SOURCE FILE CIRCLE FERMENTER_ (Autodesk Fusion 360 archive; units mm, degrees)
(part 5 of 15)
sketch "Schizzo3" plane through (-180, 0, 0) normal (-1, 0, 0) x axis (0, -1, 0)
  line L1 (-70, 14) -> (70, 14)
  line L2 (69.3077, 4.1796) -> (61.1321, 9.9042)
  line L3 (70.7767, 9.9042) -> (61.1321, 9.9042)
  line L4 (69.3077, 23.8204) -> (61.1321, 18.0958)
  line L5 (-43.1586, 69.1121) -> (-34.1131, 64.8941)
  line L6 (-26.1492, 78.9324) -> (-27.019, 68.9898)
  line L7 (-26.1492, -50.9324) -> (-27.019, -40.9898)
  line L8 (-43.1586, -41.1121) -> (-34.1131, -36.8941)
  circle C1 centre (0, 14) radius 70
  circle C2 centre (0, 14) radius 78
  circle C3 centre (0, 14) radius 70
  arc A1 centre (64, 14) radius 5 clockwise from (66.8679, 9.9042) to (61.1321, 18.0958)
  arc A2 centre (-32, 69.4256) radius 5 clockwise from (-29.8869, 73.9572) to (-34.1131, 64.8941)
  arc A3 centre (-32, -41.4256) radius 5
  point P4 (70, 14)
  point P5 (-70, 14)
  point P3 (0, 14)
  point P6 (64, 14)
  point P7 (61.1321, 9.9042)
  point P10 (61.1321, 18.0958)
  point P8 (69.3077, 4.1796)
  point P11 (69.3077, 23.8204)
  point P12 (66.8679, 9.9042)
  coincident C3 P4
  coincident C3 P5
  horizontal L1
  coincident P3 L1
  coincident L1 P6
  horizontal L3
  coincident P7 A1
  tangent L2 A1
  symmetric L1 P7 P10
  symmetric L1 P8 P11
  coincident L3 P12
  coincident C3 P11
  dimension "d1125" diameter A1 = 10
  dimension "d1126" distance P4 P6 = 6
  dimension "d1127" angle L2 L3 = 35
  dimension "d1129" C-Pattern1-Angle = 360
extrude "Estrusione4" add sketch "Schizzo3" profile of C1 C3 A1 L2 L4 L5 A2 L6 L7 A3 L8 against normal blind 15
sketch "Schizzo4" plane through (-180, 0, 0) normal (-1, 0, 0) x axis (0, -1, 0)
  line L1 (61.1321, 18.0958) -> (69.3077, 23.8204)
  line L2 (69.3077, 4.1796) -> (61.1321, 9.9042)
  line L3 (-27.019, -40.9898) -> (-26.1492, -50.9324)
  line L4 (-43.1586, -41.1121) -> (-34.1131, -36.8941)
  line L5 (-34.1131, 64.8941) -> (-43.1586, 69.1121)
  line L6 (-26.1492, 78.9324) -> (-27.019, 68.9898)
  arc A1 centre (0, 14) radius 70 clockwise from (-26.1492, 78.9324) to (69.3077, 23.8204)
  arc A2 centre (64, 14) radius 5 clockwise from (61.1321, 9.9042) to (61.1321, 18.0958)
  arc A3 centre (0, 14) radius 70 clockwise from (69.3077, 4.1796) to (-26.1492, -50.9324)
  arc A4 centre (-32, -41.4256) radius 5 clockwise from (-34.1131, -36.8941) to (-27.019, -40.9898)
  arc A5 centre (0, 14) radius 70 clockwise from (-43.1586, -41.1121) to (-43.1586, 69.1121)
  arc A6 centre (-32, 69.4256) radius 5 clockwise from (-27.019, 68.9898) to (-34.1131, 64.8941)
  circle C1 centre (0, 14) radius 78
hole "Foratura1" HoleDepth 12 HoleDiameter 3.5 TipAngle 180
position "Posizione1"
sketch "Schizzo4" plane through (-180, 0, 0) normal (1, 0, 0) x axis (0, 1, 0)
  line L1 (-36.4, -31.9) -> (36.4, -31.9)
  line L2 (-42.9, 53.4) -> (-42.9, -25.4)
  line L3 (36.4, 59.9) -> (-36.4, 59.9)
  line L4 (42.9, -25.4) -> (42.9, 53.4)
  line L5 (65, -86.5) -> (-65, -86.5)
  curve K1 (88, -63.5) -> (65, -86.5)
  line L6 (88, -56.2402) -> (88, -63.5)
  line L7 (79.4522, -45.6213) -> (86.5355, -52.7047)
  line L8 (86.5355, -34.2953) -> (79.4522, -41.3787)
  line L9 (88, 58.7598) -> (88, -30.7598)
  line L10 (79.4522, 69.3787) -> (86.5355, 62.2953)
  line L11 (86.5355, 80.7047) -> (79.4522, 73.6213)
  line L12 (88, 91.5) -> (88, 84.2402)
  curve K2 (65, 114.5) -> (88, 91.5)
  line L13 (-65, 114.5) -> (65, 114.5)
  curve K3 (-65, 114.5) -> (-88, 91.5)
  line L14 (-88, 84.2402) -> (-88, 91.5)
  line L15 (-79.4522, 73.6213) -> (-86.5355, 80.7047)
  line L16 (-86.5355, 62.2953) -> (-79.4522, 69.3787)
  line L17 (-88, -30.7598) -> (-88, 58.7598)
  line L18 (-79.4522, -41.3787) -> (-86.5355, -34.2953)
  line L19 (-86.5355, -52.7047) -> (-79.4522, -45.6213)
  line L20 (-88, -63.5) -> (-88, -56.2402)
  curve K4 (-88, -63.5) -> (-65, -86.5)
  arc A1 centre (-36.4, -25.4) radius 6.5 clockwise from (-36.4, -31.9) to (-42.9, -25.4)
  arc A2 centre (-36.4, 53.4) radius 6.5 clockwise from (-42.9, 53.4) to (-36.4, 59.9)
  arc A3 centre (36.4, 53.4) radius 6.5 clockwise from (36.4, 59.9) to (42.9, 53.4)
  arc A4 centre (36.4, -25.4) radius 6.5 clockwise from (42.9, -25.4) to (36.4, -31.9)
  circle C1 centre (25, 110.9) radius 1.75
  circle C2 centre (84.4, -11) radius 1.75
  circle C3 centre (25, -82.9) radius 1.75
  circle C4 centre (84.4, 39) radius 1.75
  circle C5 centre (-84.4, 39) radius 1.75
  circle C6 centre (-25, -82.9) radius 1.75
  circle C7 centre (-84.4, -11) radius 1.75
  circle C8 centre (-25, 110.9) radius 1.75
  arc A5 centre (83, -56.2402) radius 5 clockwise from (86.5355, -52.7047) to (88, -56.2402)
  arc A6 centre (81.5735, -43.5) radius 3 clockwise from (79.4522, -45.6213) to (79.4522, -41.3787)
  arc A7 centre (83, -30.7598) radius 5 clockwise from (88, -30.7598) to (86.5355, -34.2953)
  arc A8 centre (83, 58.7598) radius 5 clockwise from (86.5355, 62.2953) to (88, 58.7598)
  arc A9 centre (81.5735, 71.5) radius 3 clockwise from (79.4522, 69.3787) to (79.4522, 73.6213)
  arc A10 centre (83, 84.2402) radius 5 clockwise from (88, 84.2402) to (86.5355, 80.7047)
  arc A11 centre (-83, 84.2402) radius 5 clockwise from (-86.5355, 80.7047) to (-88, 84.2402)
  arc A12 centre (-81.5735, 71.5) radius 3 clockwise from (-79.4522, 73.6213) to (-79.4522, 69.3787)
  arc A13 centre (-83, 58.7598) radius 5 clockwise from (-88, 58.7598) to (-86.5355, 62.2953)
  arc A14 centre (-83, -30.7598) radius 5 clockwise from (-86.5355, -34.2953) to (-88, -30.7598)
  arc A15 centre (-81.5735, -43.5) radius 3 clockwise from (-79.4522, -41.3787) to (-79.4522, -45.6213)
  arc A16 centre (-83, -56.2402) radius 5 clockwise from (-88, -56.2402) to (-86.5355, -52.7047)
  circle C9 centre (55.4256, 46) radius 1.75
  circle C10 centre (-55.4256, 46) radius 1.75
  circle C11 centre (0, -50) radius 1.75
extrude "Estrusione2" cut sketch "Schizzo4" profile of C9 C10 C11 against normal blind 49.402
thread "Filettatura1"
sketch "Schizzo1" plane through (0, 0, -86.9) normal (0, 0, -1) x axis (1, 0, 0)
  line L1 (95, -64.5) -> (-95, -64.5)
  curve K1 (95, -64.5) -> (134.5, -25)
  line L2 (134.5, 25) -> (134.5, -25)
  curve K2 (95, 64.5) -> (134.5, 25)
  line L3 (-95, 64.5) -> (95, 64.5)
  curve K3 (-95, 64.5) -> (-134.5, 25)
  line L4 (-134.5, -25) -> (-134.5, 25)
  curve K4 (-95, -64.5) -> (-134.5, -25)
  curve K5 (95, -55) -> (125, -25)
  line L5 (95, -55) -> (0, -55)
  line L6 (-95, -55) -> (0, -55)
  curve K6 (-95, -55) -> (-125, -25)
  line L7 (-125, 25) -> (-125, -25)
  curve K7 (-95, 55) -> (-125, 25)
  line L8 (-95, 55) -> (0, 55)
  line L9 (95, 55) -> (0, 55)
  curve K8 (95, 55) -> (125, 25)
  line L10 (125, -25) -> (125, 25)
  line L11 (-125, 0) -> (125, 0)
  line L12 (100, -30) -> (100, 0)
  line L13 (20, -30) -> (100, -30)
  line L14 (-100, -15) -> (20, -30)
  line L15 (-100, 0) -> (-100, -15)
  line L16 (100, 30) -> (100, 0)
  line L17 (20, 30) -> (100, 30)
  line L18 (-100, 15) -> (20, 30)
  line L19 (-100, 0) -> (-100, 15)
  line L20 (-98.4, 0) -> (-98.4, -13.5875)
  line L21 (-98.4, 0) -> (-98.4, 13.5875)
  line L22 (-98.4, 13.5875) -> (20.0996, 28.4)
  line L23 (20.0996, 28.4) -> (98.4, 28.4)
  line L24 (98.4, 28.4) -> (98.4, 0)
  line L25 (98.4, -28.4) -> (98.4, 0)
  line L26 (20.0996, -28.4) -> (98.4, -28.4)
  line L27 (-98.4, -13.5875) -> (20.0996, -28.4)
  circle C1 centre (-130, 25) radius 1.75
  circle C2 centre (-95, 60) radius 1.75
  circle C3 centre (-32, 60) radius 1.75
  circle C4 centre (-32, -60) radius 1.75
  circle C5 centre (-95, -60) radius 1.75
  circle C6 centre (-130, -25) radius 1.75
  circle C7 centre (130, -25) radius 1.75
  circle C8 centre (95, -60) radius 1.75
  circle C9 centre (32, -60) radius 1.75
  circle C10 centre (32, 60) radius 1.75
  circle C11 centre (95, 60) radius 1.75
  circle C12 centre (130, 25) radius 1.75
  point P34 (125, 0)
  point P35 (-125, 0)
  point P36 (100, 0)
  point P40 (-100, 0)
  point P41 (100, 0)
  point P37 (100, -30)
  point P42 (100, 30)
  point P38 (20, -30)
  point P43 (20, 30)
  point P39 (-100, -15)
  point P44 (-100, 15)
  point P45 (-100, 0)
  midpoint L10 P34
  midpoint L7 P35
  coincident L11 P36
  perpendicular L11 L12
  perpendicular L12 L13
  coincident L11 P40
  perpendicular L11 L15
  symmetric L11 P36 P41
  symmetric L11 P37 P42
  symmetric L11 P38 P43
  symmetric L11 P39 P44
  symmetric L11 P40 P45
  dimension "d1137" distance L10 L12 = 25
  dimension "d1138" distance L5 L13 = 25
  dimension "d1139" distance P37 P38 = 80
  dimension "d1140" distance P39 P40 = 15
  dimension "d1142" distance L7 L15 = 25
  dimension "d1143" = 1.6
extrude "Estrusione1" new body sketch "Schizzo1" profile of L12 L13 L14 L15 L16 L17 L18 L19 L21 L20 L23 L22 L24 L25 L26 L27 along normal blind 15
fillet "Raccordo1" radius 10 100
fillet "Raccordo2" radius 5
shell "Svuotamento1" innerThickness 1.6
work_plane "Piano di lavoro1" AlongDistance -30
sketch "Schizzo2" plane through (70, 0, 0) normal (1, 0, 0) x axis (0, 1, 0)
  line L1 (-30, -101.9) -> (-30, -86.9)
  line L2 (-30, -86.9) -> (-30, -101.9)
  line L3 (-38, -86.9) -> (-30, -86.9)
  curve K1 (-38, -91.9) -> (-38, -86.9)
  curve K2 (-34, -94.4) -> (-38, -91.9)
  curve K3 (-30, -96.9) -> (-34, -94.4)
  curve K4 (-30, -101.9) -> (-30, -96.9)
  curve K5 (-30, -101.9) -> (-38, -86.9)
  line L4 (-29.6, -86.9) -> (-30, -86.9)
  line L5 (-29.6, -101.9) -> (-29.6, -86.9)
  line L6 (-30, -101.9) -> (-29.6, -101.9)
  point P2 (-30, -86.9)
  point P4 (-30, -86.9)
  point P8 (-30, -96.9)
  point P9 (-30, -86.9)
  point P3 (-30, -101.9)
  point P12 (-30, -101.9)
  point P5 (-38, -86.9)
  point P6 (-38, -91.9)
  point P10 (-29.6, -86.9)
  coincident P2 P4
  perpendicular L2 L3
  coincident L1 P8
  vertical K1
  parallel K2 K3
  equal K2 K3
  coincident P2 P9
  perpendicular L2 L4
  coincident P3 P12
  vertical L5
  horizontal L6
  dimension "d1154" distance P4 P5 = 8
  dimension "d1155" distance P3 P8 = 5
  dimension "d1156" distance P5 P6 = 5
  dimension "d1163" distance P9 P10 = 0.4
sweep "Sweep1" sketch "Schizzo2" TwistAngle 0 TaperAngle 0
sketch "Schizzo3" plane through (0, 0, -86.9) normal (0, 0, 1) x axis (-1, 0, 0)
  line L1 (-108, -20) -> (-108, 20)
  curve K1 (-90, -38) -> (-108, -20)
  line L2 (-26.2258, -38) -> (-90, -38)
  line L3 (96.6125, -23.4857) -> (-12.83, -37.166)
  line L4 (108, 10.5861) -> (108, -10.5861)
  line L5 (-12.83, 37.166) -> (96.6125, 23.4857)
  line L6 (-90, 38) -> (-26.2258, 38)
  curve K2 (-108, 20) -> (-90, 38)
  line L7 (-90, -28.4) -> (-26.2258, -28.4)
  curve K3 (-98.4, -20) -> (-90, -28.4)
  line L8 (-98.4, 20) -> (-98.4, -20)
  curve K4 (-90, 28.4) -> (-98.4, 20)
  line L9 (-26.2258, 28.4) -> (-90, 28.4)
  line L10 (95.4217, 13.9598) -> (-14.0208, 27.6401)
  line L11 (98.4, -10.5861) -> (98.4, 10.5861)
  line L12 (-14.0208, -27.6401) -> (95.4217, -13.9598)
  line L13 (36.109, 0) -> (98.4, 0)
  arc A1 centre (-26.2258, 70) radius 108 clockwise from (-12.83, -37.166) to (-26.2258, -38)
  arc A2 centre (95, -10.5861) radius 13 clockwise from (108, -10.5861) to (96.6125, -23.4857)
  arc A3 centre (95, 10.5861) radius 13 clockwise from (96.6125, 23.4857) to (108, 10.5861)
  arc A4 centre (-26.2258, -70) radius 108 clockwise from (-26.2258, 38) to (-12.83, 37.166)
  arc A5 centre (-26.2258, 70) radius 98.4 clockwise from (-14.0208, -27.6401) to (-26.2258, -28.4)
  arc A6 centre (-26.2258, -70) radius 98.4 clockwise from (-26.2258, 28.4) to (-14.0208, 27.6401)
  arc A7 centre (95, 10.5861) radius 3.4 clockwise from (95.4217, 13.9598) to (98.4, 10.5861)
  arc A8 centre (95, -10.5861) radius 3.4 clockwise from (98.4, -10.5861) to (95.4217, -13.9598)
  circle C1 centre (83.4, 0) radius 10
  arc A9 centre (83.4, 0) radius 15.3431 clockwise from (85.3031, -15.2247) to (85.3031, 15.2247)
  point P30 (98.4, 0)
  point P32 (83.4, 0)
  point P34 (85.3031, 15.2247)
  point P35 (85.3031, -15.2247)
  midpoint L11 P30
  perpendicular L11 L13
  coincident L13 P32
  concentric C1 A9
  tangent L10 A9
  coincident L10 P34
  coincident L12 P35
  dimension "d1164" diameter C1 = 20
  dimension "d1165" distance P30 P32 = 15
extrude "Estrusione2" add sketch "Schizzo3" profile of L10 A7 L11 A8 L12 C1 A9 to an object
fillet "Raccordo3" radius 2
sketch "Schizzo4" plane through (0, 0, -86.9) normal (0, 0, 1) x axis (-1, 0, 0)
  line L1 (-108, -20) -> (-108, 20)
  curve K1 (-90, -38) -> (-108, -20)
  line L2 (-26.2258, -38) -> (-90, -38)
  line L3 (96.6125, -23.4857) -> (-12.83, -37.166)
  line L4 (108, 10.5861) -> (108, -10.5861)
  line L5 (-12.83, 37.166) -> (96.6125, 23.4857)
  line L6 (-90, 38) -> (-26.2258, 38)
  curve K2 (-108, 20) -> (-90, 38)
  line L7 (-90, -28.4) -> (-26.2258, -28.4)
  curve K3 (-98.4, -20) -> (-90, -28.4)
  line L8 (-98.4, 20) -> (-98.4, -20)
  curve K4 (-90, 28.4) -> (-98.4, 20)
  line L9 (-26.2258, 28.4) -> (-90, 28.4)
  line L10 (74.3096, 16.5988) -> (-14.0208, 27.6401)
  line L11 (-14.0208, -27.6401) -> (74.3096, -16.5988)
  line L12 (108, -10) -> (83.4, -10)
  line L13 (108, 10) -> (83.4, 10)
  circle C1 centre (83.4, 0) radius 10
  arc A1 centre (-26.2258, 70) radius 108 clockwise from (-12.83, -37.166) to (-26.2258, -38)
  arc A2 centre (95, -10.5861) radius 13 clockwise from (108, -10.5861) to (96.6125, -23.4857)
  arc A3 centre (95, 10.5861) radius 13 clockwise from (96.6125, 23.4857) to (108, 10.5861)
  arc A4 centre (-26.2258, -70) radius 108 clockwise from (-26.2258, 38) to (-12.83, 37.166)
  arc A5 centre (-26.2258, 70) radius 98.4 clockwise from (-14.0208, -27.6401) to (-26.2258, -28.4)
  arc A6 centre (-26.2258, -70) radius 98.4 clockwise from (-26.2258, 28.4) to (-14.0208, 27.6401)
  arc A7 centre (74.0615, 14.6143) radius 2 clockwise from (74.3096, 16.5988) to (75.1384, 12.929)
  arc A8 centre (83.4, 0) radius 15.3431 clockwise from (75.1384, -12.929) to (75.1384, 12.929)
  arc A9 centre (74.0615, -14.6143) radius 2 clockwise from (75.1384, -12.929) to (74.3096, -16.5988)
  circle C2 centre (83.4, 0) radius 10
  point P34 (83.4, -10)
  point P35 (108, -10)
  point P36 (83.4, 10)
  point P37 (108, 10)
  coincident C1 P34
  coincident L4 P35
  tangent C1 L12
  perpendicular L4 L12
  coincident C2 P36
  coincident L4 P37
  tangent C1 L13
  perpendicular L4 L13
extrude "Estrusione3" cut sketch "Schizzo4" profile of C1 L4 C2 L12 L13 against normal blind 3.5
sketch "Schizzo5" plane through (0, 0, -100.3) normal (0, 0, 1) x axis (-1, 0, 0)
  circle C1 centre (83.4, 0) radius 10
  circle C2 centre (83.4, 0) radius 4.8
  circle C3 centre (83.4, 0) radius 6.4
  concentric C1 C2
  dimension "d1172" diameter C2 = 9.6 (= "4.8 mm * 2")
  dimension "d1173" = 1.6
extrude "Estrusione4" add sketch "Schizzo5" profile of C2 C3 along normal blind 9
sketch "Schizzo6" plane through (0, 0, -91.3) normal (0, 0, 1) x axis (-1, 0, 0)
  line L1 (83.4, 6.4) -> (83.4, 0)
  line L2 (89.8, 0) -> (83.4, 0)
  line L3 (87.9255, 4.5255) -> (83.4, 0)
  line L4 (87.1785, 0) -> (83.4, 0)
  line L5 (78.8745, 4.5255) -> (83.4, 0)
  line L6 (87.9255, -4.5255) -> (83.4, 0)
  line L7 (78.8745, -4.5255) -> (83.4, 0)
  line L8 (77, 0) -> (83.4, 0)
  line L9 (83.4, -6.4) -> (83.4, 0)
  circle C1 centre (83.4, 0) radius 4.8
  circle C2 centre (83.4, 0) radius 6.4
  point P2 (83.4, 0)
  point P3 (83.4, 0)
  point P4 (83.4, 6.4)
  point P5 (83.4, 0)
  point P6 (89.8, 0)
  point P7 (87.9255, 4.5255)
  point P9 (83.4, 0)
  point P10 (78.8745, 4.5255)
  point P11 (83.4, 0)
  point P12 (87.9255, -4.5255)
  point P13 (83.4, 0)
  point P14 (78.8745, -4.5255)
  point P15 (77, 0)
  point P16 (83.4, -6.4)
  coincident P2 P3
  coincident C2 P4
  vertical L1
  coincident P2 P5
  coincident C2 P6
  perpendicular L1 L2
  horizontal L4
  coincident C2 P7
  symmetric L1 P5 P9
  symmetric L1 P7 P10
  symmetric P5 L4 P11
  symmetric P7 L4 P12
  symmetric L4 P9 P13
  symmetric L4 P10 P14
  coincident C2 P15
  horizontal L8
  coincident C2 P16
  perpendicular L2 L9
  dimension "d1176" angle L3 L4 = 45
extrude "Estrusione5" cut sketch "Schizzo6" profile of C1 C2 L1 L2 L3 L5 L6 L7 L8 L9 against normal blind 9
fillet "Raccordo4" radius 2 0.5 2 1
sketch "Schizzo7" plane through (0, 0, -100.3) normal (0, 0, 1) x axis (-1, 0, 0)
  curve K1 (79.9502, -4.864) -> (76.9783, -5.415)
  curve K2 (75.0302, -0.7119) -> (77.5212, 1)
  line L1 (80.7847, 1) -> (77.5212, 1)
  line L2 (79.9502, -4.864) -> (82.2578, -2.5564)
  curve K3 (86.8498, 4.864) -> (89.8217, 5.415)
  curve K4 (91.7698, 0.7119) -> (89.2788, -1)
  line L3 (86.0153, -1) -> (89.2788, -1)
  line L4 (86.8498, 4.864) -> (84.5422, 2.5564)
  curve K5 (88.264, -3.4498) -> (88.815, -6.4217)
  curve K6 (84.1119, -8.3698) -> (82.4, -5.8788)
  line L5 (82.4, -2.6153) -> (82.4, -5.8788)
  line L6 (88.264, -3.4498) -> (85.9564, -1.1422)
  curve K7 (78.536, 3.4498) -> (77.985, 6.4217)
  curve K8 (82.6881, 8.3698) -> (84.4, 5.8788)
  line L7 (84.4, 2.6153) -> (84.4, 5.8788)
  line L8 (78.536, 3.4498) -> (80.8436, 1.1422)
  arc A1 centre (83.4, 0) radius 8.4 clockwise from (76.9783, -5.415) to (75.0302, -0.7119)
  arc A2 centre (83.4, 0) radius 2.8 clockwise from (82.2578, -2.5564) to (80.7847, 1)
  circle C1 centre (83.4, 0) radius 10
  circle C2 centre (83.4, 0) radius 9
  arc A3 centre (83.4, 0) radius 8.4 clockwise from (89.8217, 5.415) to (91.7698, 0.7119)
  arc A4 centre (83.4, 0) radius 2.8 clockwise from (84.5422, 2.5564) to (86.0153, -1)
  arc A5 centre (83.4, 0) radius 8.4 clockwise from (88.815, -6.4217) to (84.1119, -8.3698)
  arc A6 centre (83.4, 0) radius 2.8 clockwise from (85.9564, -1.1422) to (82.4, -2.6153)
  arc A7 centre (83.4, 0) radius 8.4 clockwise from (77.985, 6.4217) to (82.6881, 8.3698)
  arc A8 centre (83.4, 0) radius 2.8 clockwise from (80.8436, 1.1422) to (84.4, 2.6153)
  concentric A1 C2
  dimension "d1185" diameter C2 = 18
extrude "Estrusione6" add sketch "Schizzo7" profile of C1 C2 along normal blind 9.9
sketch "Schizzo8" plane through (0, 0, -90.4) normal (0, 0, 1) x axis (-1, 0, 0)
  line L1 (107.1579, -10) -> (107.1579, 10)
  line L2 (83.4, 10) -> (107.1579, 10)
  line L3 (107.1579, -10) -> (83.4, -10)
  line L4 (107.1579, -4) -> (92.5652, -4)
  line L5 (107.1579, 0) -> (83.4, 0)
  line L6 (107.1579, 4) -> (92.5652, 4)
  circle C1 centre (83.4, 0) radius 9
  arc A1 centre (83.4, 0) radius 10 clockwise from (83.4, -10) to (83.4, 10)
  circle C2 centre (83.4, 0) radius 10
  point P6 (83.4, -10)
  point P8 (92.5652, -4)
  point P9 (107.1579, -4)
  point P7 (83.4, 0)
  point P10 (83.4, 0)
  point P11 (107.1579, 0)
  point P12 (92.5652, 4)
  point P13 (107.1579, 4)
  concentric C1 C2
  coincident P6 C2
  coincident C2 P8
  coincident L1 P9
  perpendicular L1 L4
  coincident P7 P10
  midpoint L1 P11
  symmetric P8 L5 P12
  symmetric P9 L5 P13
  dimension "d1188" distance L4 L5 = 4
extrude "Estrusione7" add sketch "Schizzo8" profile of L1 L2 L3 C2 L4 L6 along normal blind 3.5
fillet "Raccordo5" radius 2
extrude "Estrusione8" add of existing geometry blind 6
extrude "Estrusione9" add of existing geometry blind 6
sketch "Schizzo9" plane through (0, 0, -86.9) normal (0, 0, 1) x axis (-1, 0, 0)
  line L1 (-90, -28.4) -> (-26.2258, -28.4)
  curve K1 (-98.4, -20) -> (-90, -28.4)
  line L2 (-98.4, 20) -> (-98.4, -20)
  curve K2 (-90, 28.4) -> (-98.4, 20)
  line L3 (-26.2258, 28.4) -> (-90, 28.4)
  line L4 (74.3096, 16.5988) -> (-14.0208, 27.6401)
  line L5 (-14.0208, -27.6401) -> (74.3096, -16.5988)
  line L6 (108, 4) -> (93.7923, 4)
  line L7 (108, 10) -> (108, 4)
  line L8 (108, 10.5861) -> (108, 10)
  line L9 (-12.83, 37.166) -> (96.6125, 23.4857)
  line L10 (-90, 38) -> (-26.2258, 38)
  curve K3 (-108, 20) -> (-90, 38)
  line L11 (-108, -20) -> (-108, 20)
  curve K4 (-90, -38) -> (-108, -20)
  line L12 (-26.2258, -38) -> (-90, -38)
  line L13 (96.6125, -23.4857) -> (-12.83, -37.166)
  line L14 (108, -10) -> (108, -10.5861)
  line L15 (108, -4) -> (108, -10)
  line L16 (93.7923, -4) -> (108, -4)
  line L17 (72.5508, 10.8492) -> (83.4, 0)
  line L18 (59.2743, 0) -> (83.4, 0)
  line L19 (107.1579, -4) -> (93.7923, -4)
  line L20 (107.1579, -4) -> (107.1579, 4)
  line L21 (93.7923, 4) -> (107.1579, 4)
  line L22 (72.5508, -10.8492) -> (83.4, 0)
  arc A1 centre (-26.2258, 70) radius 98.4 clockwise from (-14.0208, -27.6401) to (-26.2258, -28.4)
  arc A2 centre (-26.2258, -70) radius 98.4 clockwise from (-26.2258, 28.4) to (-14.0208, 27.6401)
  arc A3 centre (74.0615, 14.6143) radius 2 clockwise from (74.3096, 16.5988) to (75.1384, 12.929)
  arc A4 centre (83.4, 0) radius 15.3431 clockwise from (75.1384, -12.929) to (75.1384, 12.929)
  arc A5 centre (74.0615, -14.6143) radius 2 clockwise from (75.1384, -12.929) to (74.3096, -16.5988)
  arc A6 centre (93.7923, -6) radius 2 clockwise from (92.0603, -5) to (93.7923, -4)
  arc A7 centre (83.4, 0) radius 10 clockwise from (92.0603, -5) to (92.0603, 5)
  arc A8 centre (93.7923, 6) radius 2 clockwise from (93.7923, 4) to (92.0603, 5)
  arc A9 centre (95, 10.5861) radius 13 clockwise from (96.6125, 23.4857) to (108, 10.5861)
  arc A10 centre (-26.2258, -70) radius 108 clockwise from (-26.2258, 38) to (-12.83, 37.166)
  arc A11 centre (-26.2258, 70) radius 108 clockwise from (-12.83, -37.166) to (-26.2258, -38)
  arc A12 centre (95, -10.5861) radius 13 clockwise from (108, -10.5861) to (96.6125, -23.4857)
  arc A13 centre (83.4, 0) radius 10 clockwise from (92.0603, -5) to (92.0603, 5)
  arc A14 centre (93.7923, -6) radius 2 clockwise from (92.0603, -5) to (93.7923, -4)
  arc A15 centre (93.7923, 6) radius 2 clockwise from (93.7923, 4) to (92.0603, 5)
  circle C1 centre (83.4, 0) radius 9
  point P16 (83.4, 0)
  point P43 (83.4, 0)
  point P44 (72.5508, 10.8492)
  point P45 (83.4, 0)
  point P56 (83.4, 0)
  point P57 (72.5508, -10.8492)
  coincident P16 P43
  coincident A4 P44
  coincident P16 P45
  horizontal L18
  symmetric P43 L18 P56
  symmetric P44 L18 P57
  dimension "d1199" angle L17 L18 = 45
extrude "Estrusione10" cut sketch "Schizzo9" profile of A4 A7 L17 A13 C1 L22 to an object
fillet "Raccordo6" radius 3 0.5
sketch "Schizzo10" plane through (0, 0, -86.9) normal (0, 0, 1) x axis (-1, 0, 0)
  line L1 (74.9212, -8.4788) -> (75.9838, -7.4162)
  line L2 (-14.0208, -27.6401) -> (74.3096, -16.5988)
  line L3 (-90, -28.4) -> (-26.2258, -28.4)
  curve K1 (-98.4, -20) -> (-90, -28.4)
  line L4 (-98.4, 20) -> (-98.4, -20)
  curve K2 (-90, 28.4) -> (-98.4, 20)
  line L5 (-26.2258, 28.4) -> (-90, 28.4)
  line L6 (74.3096, 16.5988) -> (-14.0208, 27.6401)
  line L7 (75.9838, 7.4162) -> (74.9212, 8.4788)
  line L8 (108, 4) -> (93.7923, 4)
  line L9 (108, 10) -> (108, 4)
  line L10 (108, 10.5861) -> (108, 10)
  line L11 (-12.83, 37.166) -> (96.6125, 23.4857)
  line L12 (-90, 38) -> (-26.2258, 38)
  curve K3 (-108, 20) -> (-90, 38)
  line L13 (-108, -20) -> (-108, 20)
  curve K4 (-90, -38) -> (-108, -20)
  line L14 (-26.2258, -38) -> (-90, -38)
  line L15 (96.6125, -23.4857) -> (-12.83, -37.166)
  line L16 (108, -10) -> (108, -10.5861)
  line L17 (108, -4) -> (108, -10)
  line L18 (93.7923, -4) -> (108, -4)
  line L19 (-98.4, 0) -> (-108, 0)
  line L20 (-41.6241, -38) -> (-41.6241, -28.4)
  line L21 (-101.9, -16) -> (-101.9, 0)
  arc A1 centre (76.3374, -7.7698) radius 0.5 clockwise from (75.9838, -7.4162) to (76.6737, -7.3998)
  arc A2 centre (77.0425, -10.6001) radius 3 clockwise from (75.2539, -13.0086) to (74.9212, -8.4788)
  arc A3 centre (74.0615, -14.6143) radius 2 clockwise from (75.2539, -13.0086) to (74.3096, -16.5988)
  arc A4 centre (-26.2258, 70) radius 98.4 clockwise from (-14.0208, -27.6401) to (-26.2258, -28.4)
  arc A5 centre (-26.2258, -70) radius 98.4 clockwise from (-26.2258, 28.4) to (-14.0208, 27.6401)
  arc A6 centre (74.0615, 14.6143) radius 2 clockwise from (74.3096, 16.5988) to (75.2539, 13.0086)
  arc A7 centre (77.0425, 10.6001) radius 3 clockwise from (74.9212, 8.4788) to (75.2539, 13.0086)
  arc A8 centre (76.3374, 7.7698) radius 0.5 clockwise from (76.6737, 7.3998) to (75.9838, 7.4162)
  arc A9 centre (83.4, 0) radius 10 clockwise from (76.6737, 7.3998) to (92.0603, 5)
  arc A10 centre (93.7923, 6) radius 2 clockwise from (93.7923, 4) to (92.0603, 5)
  arc A11 centre (95, 10.5861) radius 13 clockwise from (96.6125, 23.4857) to (108, 10.5861)
  arc A12 centre (-26.2258, -70) radius 108 clockwise from (-26.2258, 38) to (-12.83, 37.166)
  arc A13 centre (-26.2258, 70) radius 108 clockwise from (-12.83, -37.166) to (-26.2258, -38)
  arc A14 centre (95, -10.5861) radius 13 clockwise from (108, -10.5861) to (96.6125, -23.4857)
  arc A15 centre (93.7923, -6) radius 2 clockwise from (92.0603, -5) to (93.7923, -4)
  arc A16 centre (83.4, 0) radius 10 clockwise from (92.0603, -5) to (76.6737, -7.3998)
  circle C1 centre (88, -16) radius 1.5
  circle C2 centre (-101.9, -16) radius 1.5
  point P53 (-108, 0)
  point P54 (-98.4, 0)
  point P55 (-41.6241, -28.4)
  point P56 (-41.6241, -38)
  point P58 (-101.9, -16)
  point P60 (-101.9, -16)
  point P59 (-101.9, 0)
  point P29 (83.4, 0)
  point P57 (88, -16)
  midpoint L13 P53
  midpoint L4 P54
  coincident L3 P55
  coincident L14 P56
  perpendicular L14 L20
  coincident P58 P60
  vertical L21
  dimension "d1207" diameter C1 = 3
  dimension "d1208" diameter C2 = 3
  dimension "d1209" distance P59 P60 = 16
  dimension "d1210" distance P29 P57 = 16
  dimension "d1211" distance L17 P57 = 20
  dimension "d1212" distance L4 L21 = 3.5
extrude "Estrusione11" cut sketch "Schizzo10" profile of C1 C2 against normal blind 7.5
mirror "Specchio1" mirrorStitchTolerance 0.1
sketch "Schizzo2" plane through (0, 0, -83.9) normal (0, 0, 1) x axis (-1, 0, 0)
  line L1 (-95, 64.5) -> (95, 64.5)
  curve K1 (-134.5, 25) -> (-95, 64.5)
  line L2 (-134.5, -25) -> (-134.5, 25)
  curve K2 (-134.5, -25) -> (-95, -64.5)
  line L3 (95, -64.5) -> (-95, -64.5)
  curve K3 (134.5, -25) -> (95, -64.5)
  line L4 (134.5, 25) -> (134.5, -25)
  curve K4 (134.5, 25) -> (95, 64.5)
  circle C1 centre (130, 25) radius 1.75
  circle C2 centre (95, 60) radius 1.75
  circle C3 centre (32, 60) radius 1.75
  circle C4 centre (32, -60) radius 1.75
  circle C5 centre (95, -60) radius 1.75
  circle C6 centre (130, -25) radius 1.75
  circle C7 centre (-130, -25) radius 1.75
  circle C8 centre (-95, -60) radius 1.75
  circle C9 centre (-32, -60) radius 1.75
  circle C10 centre (-32, 60) radius 1.75
  circle C11 centre (-95, 60) radius 1.75
  circle C12 centre (-130, 25) radius 1.75
  circle C13 centre (88, -16) radius 1.5
  circle C14 centre (88, 16) radius 1.5
  circle C15 centre (-101.9, -16) radius 1.5
  circle C16 centre (-101.9, 16) radius 1.5
extrude "Estrusione2" cut sketch "Schizzo2" profile of C13 C14 C15 C16 against normal blind 3
thread "Filettatura1"
sketch "Schizzo11" plane through (70, 0, 0) normal (1, 0, 0) x axis (0, 1, 0)
  curve K1 (-30, -101.9) -> (-38, -86.9)
  line L1 (28.4, -86.9) -> (38, -86.9)
  line L2 (-38, -86.9) -> (-28.4, -86.9)
  circle C1 centre (-36, -87.4) radius 0.85
  point P8 (-36, -87.4)
  point P2 (-38, -86.9)
  dimension "d1217" diameter C1 = 1.7
  dimension "d1218" distance L2 P8 = 0.5
  dimension "d1219" distance P2 P8 = 2
sweep "Sweep2" sketch "Schizzo11" TwistAngle 0 TaperAngle 0
extrude "Estrusione12" add of existing geometry blind 0.2
sketch "Schizzo1" plane through (0, 0, -83.9) normal (0, 0, 1) x axis (-1, 0, 0)
  line L1 (-95, 64.5) -> (95, 64.5)
  curve K1 (-134.5, 25) -> (-95, 64.5)
  line L2 (-134.5, -25) -> (-134.5, 25)
  curve K2 (-134.5, -25) -> (-95, -64.5)
  line L3 (95, -64.5) -> (-95, -64.5)
  curve K3 (134.5, -25) -> (95, -64.5)
  line L4 (134.5, 25) -> (134.5, -25)
  curve K4 (134.5, 25) -> (95, 64.5)
  line L5 (-14.0208, 27.6401) -> (74.3096, 16.5988)
  line L6 (-90, 28.4) -> (-26.2258, 28.4)
  curve K5 (-90, 28.4) -> (-98.4, 20)
  line L7 (-98.4, -20) -> (-98.4, 20)
  curve K6 (-98.4, -20) -> (-90, -28.4)
  line L8 (-26.2258, -28.4) -> (-90, -28.4)
  line L9 (74.3096, -16.5988) -> (-14.0208, -27.6401)
  line L10 (76.6918, -6.7082) -> (74.9212, -8.4788)
  line L11 (74.9212, 8.4788) -> (76.6918, 6.7082)
  curve K7 (78.536, 3.4498) -> (77.985, 6.4217)
  curve K8 (82.6881, 8.3698) -> (84.4, 5.8788)
  line L12 (84.4, 2.6153) -> (84.4, 5.8788)
  line L13 (78.536, 3.4498) -> (80.8436, 1.1422)
  curve K9 (88.264, -3.4498) -> (88.815, -6.4217)
  curve K10 (84.1119, -8.3698) -> (82.4, -5.8788)
  line L14 (82.4, -2.6153) -> (82.4, -5.8788)
  line L15 (88.264, -3.4498) -> (85.9564, -1.1422)
  curve K11 (86.8498, 4.864) -> (89.8217, 5.415)
  curve K12 (91.7698, 0.7119) -> (89.2788, -1)
  line L16 (86.0153, -1) -> (89.2788, -1)
  line L17 (86.8498, 4.864) -> (84.5422, 2.5564)
  curve K13 (79.9502, -4.864) -> (76.9783, -5.415)
  curve K14 (75.0302, -0.7119) -> (77.5212, 1)
  line L18 (80.7847, 1) -> (77.5212, 1)
  line L19 (79.9502, -4.864) -> (82.2578, -2.5564)
  line L20 (78.2787, -16.1027) -> (74.3096, -16.5988)
  line L21 (89.206, -6.8768) -> (78.2787, -16.1027)
  line L22 (69.6016, 0) -> (83.4, 0)
  line L23 (78.2787, 16.1027) -> (74.3096, 16.5988)
  line L24 (89.206, 6.8768) -> (78.2787, 16.1027)
  circle C1 centre (130, 25) radius 1.75
  circle C2 centre (95, 60) radius 1.75
  circle C3 centre (32, 60) radius 1.75
  circle C4 centre (32, -60) radius 1.75
  circle C5 centre (95, -60) radius 1.75
  circle C6 centre (130, -25) radius 1.75
  circle C7 centre (-130, -25) radius 1.75
  circle C8 centre (-95, -60) radius 1.75
  circle C9 centre (-32, -60) radius 1.75
  circle C10 centre (-32, 60) radius 1.75
  circle C11 centre (-95, 60) radius 1.75
  circle C12 centre (-130, 25) radius 1.75
  arc A1 centre (74.0615, 14.6143) radius 2 clockwise from (74.3096, 16.5988) to (75.2539, 13.0086)
  arc A2 centre (-26.2258, -70) radius 98.4 clockwise from (-26.2258, 28.4) to (-14.0208, 27.6401)
  arc A3 centre (-26.2258, 70) radius 98.4 clockwise from (-14.0208, -27.6401) to (-26.2258, -28.4)
  arc A4 centre (74.0615, -14.6143) radius 2 clockwise from (75.2539, -13.0086) to (74.3096, -16.5988)
  arc A5 centre (77.0425, -10.6001) radius 3 clockwise from (75.2539, -13.0086) to (74.9212, -8.4788)
  arc A6 centre (77.0453, -7.0618) radius 0.5 clockwise from (76.6918, -6.7082) to (77.3798, -6.6901)
  arc A7 centre (83.4, 0) radius 9 clockwise from (77.3798, 6.6901) to (77.3798, -6.6901)
  arc A8 centre (77.0453, 7.0618) radius 0.5 clockwise from (77.3798, 6.6901) to (76.6918, 6.7082)
  arc A9 centre (77.0425, 10.6001) radius 3 clockwise from (74.9212, 8.4788) to (75.2539, 13.0086)
  arc A10 centre (83.4, 0) radius 8.4 clockwise from (77.985, 6.4217) to (82.6881, 8.3698)
  arc A11 centre (83.4, 0) radius 2.8 clockwise from (80.8436, 1.1422) to (84.4, 2.6153)
  arc A12 centre (83.4, 0) radius 8.4 clockwise from (88.815, -6.4217) to (84.1119, -8.3698)
  arc A13 centre (83.4, 0) radius 2.8 clockwise from (85.9564, -1.1422) to (82.4, -2.6153)
  arc A14 centre (83.4, 0) radius 8.4 clockwise from (89.8217, 5.415) to (91.7698, 0.7119)
  arc A15 centre (83.4, 0) radius 2.8 clockwise from (84.5422, 2.5564) to (86.0153, -1)
  arc A16 centre (83.4, 0) radius 8.4 clockwise from (76.9783, -5.415) to (75.0302, -0.7119)
  arc A17 centre (83.4, 0) radius 2.8 clockwise from (82.2578, -2.5564) to (80.7847, 1)
  circle C13 centre (83.4, 0) radius 9
  circle C14 centre (88, 16) radius 1.5
  circle C15 centre (-101.9, -16) radius 1.5
  circle C16 centre (88, -16) radius 1.5
  circle C17 centre (-101.9, 16) radius 1.5
  point P35 (74.3096, -16.5988)
  point P74 (74.3096, -16.5988)
  point P76 (89.206, -6.8768)
  point P73 (83.4, 0)
  point P77 (83.4, 0)
  point P79 (74.3096, 16.5988)
  point P75 (78.2787, -16.1027)
  point P80 (78.2787, 16.1027)
  point P81 (89.206, 6.8768)
  concentric A7 C13
  coincident P35 P74
  coincident A7 P76
  coincident C13 P76
  tangent C13 L21
  parallel L9 L20
  coincident P73 P77
  horizontal L22
  symmetric P74 L22 P79
  symmetric P75 L22 P80
  symmetric P76 L22 P81
  dimension "d1228" diameter C13 = 18
  dimension "d1229" distance P74 P75 = 4
extrude "Estrusione1" cut sketch "Schizzo1" + "Schizzo1" profile of S1:A1 S1:L5 S2:K17 S1:L6 S2:K19 S2:K20 S2:K21 S2:K22 S2:K24 S2:L8 S1:A4 S1:A5 S1:L10 S1:A6 S1:A7 S1:A8 S1:L11 S1:A9 S1:K7 S1:A10 S1:K8 S1:L12 S1:A11 S1:L13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 to an object
fillet "Raccordo1" radius 14
offset_faces "FacceDiOffset1" distance -0.25
sketch "Schizzo2" plane through (0, 0, -88.5) normal (0, 0, 1) x axis (-1, 0, 0)
  line L1 (124.4, -25) -> (124.4, 25)
  curve K1 (95, -54.4) -> (124.4, -25)
  line L2 (0, -54.4) -> (95, -54.4)
  line L3 (-2, -54.4) -> (0, -54.4)
  line L4 (-2, -59.7) -> (-2, -54.4)
  line L5 (0, -59.7) -> (-2, -59.7)
  line L6 (0, -65) -> (0, -59.7)
  line L7 (95, -65) -> (0, -65)
  curve K2 (95, -65) -> (135, -25)
  line L8 (135, 25) -> (135, -25)
  curve K3 (95, 65) -> (135, 25)
  line L9 (0, 65) -> (95, 65)
  line L10 (0, 59.7) -> (0, 65)
  line L11 (-2, 59.7) -> (0, 59.7)
  line L12 (-2, 54.4) -> (-2, 59.7)
  line L13 (0, 54.4) -> (-2, 54.4)
  line L14 (95, 54.4) -> (0, 54.4)
  curve K4 (95, 54.4) -> (124.4, 25)
  line L15 (124.4, 0) -> (135, 0)
  line L16 (124.4, 2) -> (135, 2)
  line L17 (135, 0) -> (135, 2)
  line L18 (124.4, 0) -> (124.4, 2)
  circle C1 centre (95, 60) radius 1.75
  circle C2 centre (32, 60) radius 1.75
  circle C3 centre (130, 25) radius 1.75
  circle C4 centre (130, -25) radius 1.75
  circle C5 centre (32, -60) radius 1.75
  circle C6 centre (95, -60) radius 1.75
  point P26 (135, 0)
  point P27 (124.4, 0)
  midpoint L8 P26
  midpoint L1 P27
  perpendicular L15 L17
  perpendicular L15 L18
  dimension "d1237" = 2
revolve "Rivoluzione1" sketch "Schizzo2" AlongAngle 360
extrude "Estrusione2" cut of existing geometry blind -5.446
mirror "Specchio1" sketch "Schizzo1" mirrorStitchTolerance 0.1 named "d821_1"
copy_paste "TagliaIncolla1"
sketch "Schizzo1" plane through (160, 0, 0) normal (1, 0, 0) x axis (0, 1, 0)
  line L1 (90, 116.5) -> (90, -88.5)
  line L2 (-90, 116.5) -> (90, 116.5)
  line L3 (-90, -88.5) -> (-90, 116.5)
  line L4 (90, -88.5) -> (-90, -88.5)
  curve K1 (-65, -88.5) -> (-90, -63.5)
  line L5 (-15, -88.5) -> (-65, -88.5)
  line L6 (-90, -13.5) -> (-90, -63.5)
  line L7 (-15, -86.9) -> (-65, -86.9)
  curve K2 (-65, -86.9) -> (-88.4, -63.5)
  line L8 (-88.4, -13.5) -> (-88.4, -63.5)
  line L9 (-15, -88.5) -> (-15, -86.9)
  line L10 (-88.4, -13.5) -> (-90, -13.5)
  point P7 (-65, -88.5)
  point P8 (-65, -88.5)
  point P6 (-90, -63.5)
  point P10 (-90, -63.5)
  point P9 (-15, -88.5)
  point P11 (-90, -13.5)
  coincident P7 P8
  parallel L4 L5
  coincident P6 P10
  parallel L3 L6
  perpendicular L5 L9
  dimension "d178_1" distance P8 P9 = 50
  dimension "d179_1" distance P10 P11 = 50
  dimension "d180_1" = -1.6
extrude "Estrusione1" new body sketch "Schizzo1" profile of L3 L4 K1 L5 L6 L7 K2 L8 L9 L10 against normal blind 120 named "d181_1"
sketch "Schizzo2" plane through (0, 0, -88.5) normal (0, 0, -1) x axis (1, 0, 0)
  line L1 (160, 65) -> (160, 15)
  line L2 (40, 65) -> (160, 65)
  line L3 (40, 15) -> (40, 65)
  line L4 (160, 15) -> (40, 15)
  line L5 (125, 15) -> (40, 15)
  line L6 (125, 55) -> (125, 15)
  line L7 (40, 55) -> (125, 55)
  line L8 (40, 15) -> (40, 55)
  line L9 (160, 65) -> (160, 90)
  line L10 (40, 90) -> (160, 90)
  line L11 (40, 90) -> (40, 65)
  line L12 (160, 65) -> (40, 65)
  point P5 (40, 15)
  point P6 (40, 15)
  horizontal L5
  vertical L6
  horizontal L7
  vertical L8
  coincident P5 P6
  dimension "d183_1" distance L1 L6 = 35
  dimension "d184_1" distance L7 L10 = 35
extrude "Estrusione2" cut sketch "Schizzo2" profile of L3 L4 L5 L6 L7 L8 against normal blind 2.4 named "d185_1"
sketch "Schizzo3" plane through (0, 0, -86.9) normal (0, 0, 1) x axis (-1, 0, 0)
  line L1 (-40, 55) -> (-125, 55)
  line L2 (-40, 65) -> (-40, 55)
  line L3 (-160, 65) -> (-40, 65)
  line L4 (-160, 15) -> (-160, 65)
  line L5 (-125, 15) -> (-160, 15)
  line L6 (-125, 55) -> (-125, 15)
  line L7 (-135, 65) -> (-40, 65)
  line L8 (-135, 15) -> (-135, 65)
  line L9 (-40, 15) -> (-135, 15)
  line L10 (-40, 65) -> (-40, 15)
  point P10 (-135, 15)
  point P4 (-40, 65)
  point P8 (-40, 65)
  horizontal L7
  vertical L8
  horizontal L9
  vertical L10
  coincident L5 P10
  coincident P4 P8
  dimension "d187_1" distance L6 L8 = 10
  dimension "d188_1" distance L1 L7 = 10
extrude "Estrusione3" new body sketch "Schizzo3" profile of L1 L2 L3 L5 L6 L7 L8 L9 L10 along normal blind 3 named "d189_1" bodies "TEST ACRILICO"
sketch "Schizzo4" plane through (0, -90, 0) normal (0, -1, 0) x axis (1, 0, 0)
  line L1 (160, -13.5) -> (160, -63.5)
  line L2 (40, -13.5) -> (160, -13.5)
  line L3 (40, -63.5) -> (40, -13.5)
  line L4 (160, -63.5) -> (40, -63.5)
  line L5 (160, -88.5) -> (160, -63.5)
  line L6 (40, -63.5) -> (160, -63.5)
  line L7 (40, -63.5) -> (40, -88.5)
  line L8 (160, -88.5) -> (40, -88.5)
  line L9 (125, -13.5) -> (40, -13.5)
  line L10 (125, -53.5) -> (125, -13.5)
  line L11 (40, -53.5) -> (125, -53.5)
  line L12 (40, -13.5) -> (40, -53.5)
  point P4 (40, -13.5)
  point P10 (40, -13.5)
  horizontal L9
  vertical L10
  horizontal L11
  vertical L12
  coincident P4 P10
  dimension "d191_1" distance L1 L10 = 35
  dimension "d192_1" distance L8 L11 = 35
extrude "Estrusione4" cut sketch "Schizzo4" profile of L2 L3 L9 L10 L11 L12 against normal blind 14.667 named "d193_1"
sketch "Schizzo5" plane through (0, -88.4, 0) normal (0, 1, 0) x axis (-1, 0, 0)
  line L1 (-125, -53.5) -> (-40, -53.5)
  line L2 (-125, -13.5) -> (-125, -53.5)
  line L3 (-160, -13.5) -> (-125, -13.5)
  line L4 (-160, -63.5) -> (-160, -13.5)
  line L5 (-40, -63.5) -> (-160, -63.5)
  line L6 (-40, -53.5) -> (-40, -63.5)
  line L7 (-135, -63.5) -> (-40, -63.5)
  line L8 (-135, -13.5) -> (-135, -63.5)
  line L9 (-40, -13.5) -> (-135, -13.5)
  line L10 (-40, -63.5) -> (-40, -13.5)
  point P10 (-135, -13.5)
  point P7 (-40, -63.5)
  point P8 (-40, -63.5)
  horizontal L7
  vertical L8
  horizontal L9
  vertical L10
  coincident L3 P10
  coincident P7 P8
  dimension "d195_1" distance L2 L8 = 10
extrude "Estrusione5" new body sketch "Schizzo5" profile of L1 L2 L3 L5 L6 L7 L8 L9 L10 along normal blind 3 named "d196_1" bodies "TEST ACRILICO 2"
sketch "Schizzo6" plane through (0, -90, 0) normal (0, -1, 0) x axis (1, 0, 0)
  line L1 (40, -53.5) -> (125, -53.5)
  line L2 (40, -63.5) -> (40, -53.5)
  line L3 (160, -63.5) -> (40, -63.5)
  line L4 (160, -13.5) -> (160, -63.5)
  line L5 (125, -13.5) -> (160, -13.5)
  line L6 (125, -53.5) -> (125, -13.5)
  curve K1 (110, -53.5) -> (95, -53.5)
  curve K2 (117.5, -53.5) -> (110, -53.5)
  curve K3 (125, -46) -> (117.5, -53.5)
  curve K4 (125, -38.5) -> (125, -46)
  curve K5 (125, -23.5) -> (125, -38.5)
  curve K6 (125, -23.5) -> (95, -53.5)
  point P8 (95, -53.5)
  point P9 (110, -53.5)
  point P10 (117.5, -53.5)
  point P11 (125, -46)
  point P12 (125, -38.5)
  point P13 (125, -23.5)
  point P2 (125, -53.5)
  coincident L1 P8
  coincident L1 P9
  coincident L1 P10
  coincident L6 P11
  coincident L6 P12
  coincident L6 P13
  dimension "d198_1" distance P2 P8 = 30
  dimension "d199_1" distance P2 P9 = 15
  dimension "d200_1" distance P2 P10 = 7.5
  dimension "d201_1" distance P2 P11 = 7.5 (= "d200_1")
  dimension "d202_1" distance P2 P12 = 15 (= "d199_1")
  dimension "d203_1" distance P2 P13 = 30 (= "d198_1")
extrude "Estrusione6" add sketch "Schizzo6" profile of L1 L6 K6 against normal blind 1.6 named "d204_1"
sketch "Schizzo7" plane through (0, 0, -88.5) normal (0, 0, -1) x axis (1, 0, 0)
  line L1 (125, 55) -> (40, 55)
  line L2 (125, 15) -> (125, 55)
  line L3 (160, 15) -> (125, 15)
  line L4 (160, 65) -> (160, 15)
  line L5 (40, 65) -> (160, 65)
  line L6 (40, 55) -> (40, 65)
  curve K1 (125, 40) -> (125, 25)
  curve K2 (125, 47.5) -> (125, 40)
  curve K3 (117.5, 55) -> (125, 47.5)
  curve K4 (110, 55) -> (117.5, 55)
  curve K5 (95, 55) -> (110, 55)
  curve K6 (95, 55) -> (125, 25)
  point P8 (125, 25)
  point P9 (125, 40)
  point P10 (125, 47.5)
  point P11 (117.5, 55)
  point P12 (110, 55)
  point P13 (95, 55)
  point P3 (125, 55)
  coincident L2 P8
  coincident L2 P9
  coincident L2 P10
  coincident L1 P11
  coincident L1 P12
  coincident L1 P13
  dimension "d206_1" distance P3 P13 = 30
  dimension "d207_1" distance P3 P12 = 15
  dimension "d208_1" distance P3 P11 = 7.5
  dimension "d209_1" distance P3 P10 = 7.5 (= "d208_1")
  dimension "d210_1" distance P3 P9 = 15 (= "d207_1")
  dimension "d211_1" distance P3 P8 = 30 (= "d206_1")
extrude "Estrusione7" add sketch "Schizzo7" profile of L1 L2 K6 against normal blind 1.6 named "d212_1"
sketch "Schizzo8" plane through (0, 0, -83.9) normal (0, 0, 1) x axis (-1, 0, 0)
  line L1 (-40, 65) -> (-40, 15)
  line L2 (-135, 65) -> (-40, 65)
  line L3 (-135, 15) -> (-135, 65)
  line L4 (-40, 15) -> (-135, 15)
  curve K1 (-95, 55) -> (-125, 25)
  curve K2 (-95, 65) -> (-135, 25)
  line L5 (-135, 15) -> (-135, 25)
  line L6 (-40, 65) -> (-95, 65)
  point P3 (-40, 65)
  point P11 (-40, 65)
  perpendicular L4 L5
  coincident P3 P11
  dimension "d214_1" = -10
extrude "Estrusione8" cut sketch "Schizzo8" profile of L2 L3 K2 against normal blind 3 named "d215_1"
sketch "Schizzo9" plane through (0, -85.4, 0) normal (0, 1, 0) x axis (-1, 0, 0)
  line L1 (-135, -13.5) -> (-40, -13.5)
  line L2 (-135, -63.5) -> (-135, -13.5)
  line L3 (-40, -63.5) -> (-135, -63.5)
  line L4 (-40, -13.5) -> (-40, -63.5)
  curve K1 (-125, -23.5) -> (-95, -53.5)
  curve K2 (-135, -23.5) -> (-95, -63.5)
  dimension "d217_1" = -10
extrude "Estrusione9" cut sketch "Schizzo9" profile of L2 L3 K2 against normal blind 3 named "d218_1"
sketch "Schizzo10" plane through (160, 0, 0) normal (1, 0, 0) x axis (0, 1, 0)
  curve K1 (-65, -88.5) -> (-90, -63.5)
  line L1 (-15, -88.5) -> (-65, -88.5)
  line L2 (-15, -86.9) -> (-15, -88.5)
  line L3 (-65, -86.9) -> (-15, -86.9)
  curve K2 (-65, -86.9) -> (-88.4, -63.5)
  line L4 (-88.4, -13.5) -> (-88.4, -63.5)
  line L5 (-90, -13.5) -> (-88.4, -13.5)
  line L6 (-90, -63.5) -> (-90, -13.5)
  line L7 (-25, -83.9) -> (-65, -83.9)
  line L8 (-65, -86.9) -> (-65, -83.9)
  line L9 (-65, -86.9) -> (-25, -86.9)
  line L10 (-25, -83.9) -> (-25, -86.9)
  line L11 (-85.4, -63.5) -> (-85.4, -23.5)
  line L12 (-88.4, -23.5) -> (-85.4, -23.5)
  line L13 (-88.4, -23.5) -> (-88.4, -63.5)
  line L14 (-85.4, -63.5) -> (-88.4, -63.5)
  line L15 (-90, -88.5) -> (-65, -88.5)
  line L16 (-90, -63.5) -> (-90, -88.5)
  line L17 (-63.3232, -61.8232) -> (-90, -88.5)
  line L18 (-78.4501, -76.9501) -> (-83.3998, -81.8998)
  curve K3 (-65, -83.9) -> (-85.4, -63.5)
  line L19 (-70.5446, -84.8556) -> (-78.4501, -76.9501)
  curve K4 (-74.9146, -80.4856) -> (-78.4501, -76.9501)
  curve K5 (-74.9146, -83.3141) -> (-74.9146, -80.4856)
  curve K6 (-69, -83.8545) -> (-74.9146, -83.3141)
  curve K7 (-65, -83.9) -> (-69, -83.8545)
  curve K8 (-65, -83.9) -> (-78.4501, -76.9501)
  curve K9 (-85.4, -63.5) -> (-78.4501, -76.9501)
  curve K10 (-81.9856, -73.4146) -> (-78.4501, -76.9501)
  curve K11 (-84.8141, -73.4146) -> (-81.9856, -73.4146)
  curve K12 (-85.3545, -67.5) -> (-84.8141, -73.4146)
  curve K13 (-85.4, -63.5) -> (-85.3545, -67.5)
  point P3 (-65, -88.5)
  point P18 (-65, -88.5)
  point P2 (-90, -63.5)
  point P20 (-90, -63.5)
  point P22 (-83.3998, -81.8998)
  point P23 (-78.4501, -76.9501)
  point P27 (-74.9146, -80.4856)
  point P29 (-69, -83.8545)
  point P10 (-65, -83.9)
  point P25 (-65, -83.9)
  point P31 (-85.4, -63.5)
  point P30 (-78.4501, -76.9501)
  point P28 (-74.9146, -83.3141)
  coincident P3 P18
  coincident P2 P20
  vertical L16
  coincident L17 P22
  coincident K2 P22
  coincident L17 P23
  perpendicular L18 L19
  coincident L19 P27
  coincident K3 P29
  coincident P10 P25
  symmetric P10 L17 P31
  symmetric L17 P23 P30
  symmetric L17 K8 K9
  dimension "d220_1" angle L15 L17 = 45
  dimension "d221_1" distance P22 P23 = 7
  dimension "d222_1" = -3
  dimension "d223_1" distance P27 P30 = 5
  dimension "d224_1" distance L19 P28 = 2
  dimension "d225_1" distance P25 P29 = 4
  dimension "d228_1" distance L17 P28 = 7
extrude "Estrusione10" add sketch "Schizzo10" profile of K2 L8 L14 L18 K8 K9 against normal blind 120 named "d226_1"
extrude "Estrusione11" cut sketch "Schizzo10" profile of K2 L8 L14 L18 K8 K9 against normal blind 65 named "d229_1"
sketch "Schizzo11" plane through (0, 0, -13.5) normal (0, 0, 1) x axis (-1, 0, 0)
  line L1 (-125, 90) -> (-125, 88.4)
  line L2 (-160, 90) -> (-125, 90)
  line L3 (-160, 88.4) -> (-160, 90)
  line L4 (-125, 88.4) -> (-160, 88.4)
  line L5 (-135, 88.4) -> (-40, 88.4)
  line L6 (-135, 85.4) -> (-135, 88.4)
  line L7 (-40, 85.4) -> (-135, 85.4)
  line L8 (-40, 88.4) -> (-40, 85.4)
  line L9 (-142.5, 81.4) -> (-142.5, 88.4)
  line L10 (-147.5, 81.4) -> (-142.5, 81.4)
  line L11 (-137.5, 81.4) -> (-142.5, 81.4)
  curve K1 (-154.5, 88.4) -> (-160, 88.4)
  curve K2 (-148.5, 84.9) -> (-154.5, 88.4)
  curve K3 (-146.5, 81.4) -> (-148.5, 84.9)
  curve K4 (-142.5, 81.4) -> (-146.5, 81.4)
  curve K5 (-142.5, 81.4) -> (-160, 88.4)
  curve K6 (-139.5, 81.4) -> (-142.5, 81.4)
  curve K7 (-139, 84.9) -> (-139.5, 81.4)
  curve K8 (-137, 85.4) -> (-139, 84.9)
  curve K9 (-135, 85.4) -> (-137, 85.4)
  curve K10 (-135, 85.4) -> (-142.5, 81.4)
  point P10 (-142.5, 88.4)
  point P14 (-154.5, 88.4)
  point P16 (-146.5, 81.4)
  point P17 (-139.5, 81.4)
  point P11 (-142.5, 81.4)
  point P12 (-147.5, 81.4)
  point P13 (-137.5, 81.4)
  point P15 (-148.5, 84.9)
  point P8 (-135, 85.4)
  point P19 (-137, 85.4)
  point P18 (-139, 84.9)
  midpoint L4 P10
  perpendicular L4 L9
  perpendicular L9 L10
  perpendicular L9 L11
  coincident L4 P14
  coincident L10 P16
  coincident L11 P17
  horizontal K9
  dimension "d231_1" distance P10 P11 = 7
  dimension "d232_1" distance P11 P12 = 5
  dimension "d233_1" distance P11 P13 = 5
  dimension "d234_1" distance L9 P14 = 12
  dimension "d235_1" distance L9 P15 = 6
  dimension "d236_1" distance L9 P16 = 4
  dimension "d237_1" distance L10 P15 = 3.5
  dimension "d238_1" distance P11 P17 = 3
  dimension "d239_1" distance P8 P19 = 2
  dimension "d240_1" distance L6 P18 = 4
  dimension "d241_1" distance L11 P18 = 3.5
extrude "Estrusione12" add sketch "Schizzo11" profile of L4 L6 K5 K10 against normal blind 50 named "d242_1"
work_plane "Piano di lavoro1"
mirror "Specchio1" mirrorStitchTolerance 0.1 named "d245_1"
sketch "Schizzo12" plane through (0, 0, -86.9) normal (0, 0, 1) x axis (-1, 0, 0)
  line L1 (-135, 15) -> (-135, 65)
  line L2 (-125, 15) -> (-135, 15)
  line L3 (-125, 25) -> (-125, 15)
  curve K1 (-95, 55) -> (-125, 25)
  line L4 (-40, 55) -> (-95, 55)
  line L5 (-40, 65) -> (-40, 55)
  line L6 (-95, 65) -> (-40, 65)
  line L7 (-135, 65) -> (-95, 65)
  curve K2 (-135, 25) -> (-95, 65)
  line L8 (-135, 15) -> (-135, 25)
  line L9 (-40, 15) -> (-135, 15)
  line L10 (-40, 65) -> (-40, 15)
  line L11 (-95, 65) -> (-40, 65)
extrude "Estrusione13" new body sketch "Schizzo12" profile of L1 L7 K2 along normal blind 3 named "d246_1"
sketch "Schizzo13" plane through (0, -88.4, 0) normal (0, 1, 0) x axis (-1, 0, 0)
  line L1 (-135, -63.5) -> (-135, -13.5)
  line L2 (-95, -63.5) -> (-135, -63.5)
  line L3 (-40, -63.5) -> (-95, -63.5)
  line L4 (-40, -53.5) -> (-40, -63.5)
  line L5 (-95, -53.5) -> (-40, -53.5)
  curve K1 (-125, -23.5) -> (-95, -53.5)
  line L6 (-125, -13.5) -> (-125, -23.5)
  line L7 (-135, -13.5) -> (-125, -13.5)
  curve K2 (-95, -63.5) -> (-135, -23.5)
  line L8 (-40, -63.5) -> (-95, -63.5)
  line L9 (-40, -13.5) -> (-40, -63.5)
  line L10 (-135, -13.5) -> (-40, -13.5)
  line L11 (-135, -23.5) -> (-135, -13.5)
extrude "Estrusione14" new body sketch "Schizzo13" profile of L1 L2 K2 along normal blind 3 named "d248_1"
combine "Combina1"
sketch "Schizzo14" plane through (0, -65, 0) normal (0, -1, 0) x axis (1, 0, 0)
  curve K1 (160, -86.9) -> (142.5, -79.9)
  curve K2 (142.5, -79.9) -> (135, -83.9)
  line L1 (95, -83.9) -> (135, -83.9)
  line L2 (95, -86.9) -> (95, -83.9)
  line L3 (160, -86.9) -> (95, -86.9)
  line L4 (125, -86.9) -> (125, -88.5)
  line L5 (135, -86.9) -> (125, -86.9)
  line L6 (135, -83.9) -> (135, -86.9)
  curve K3 (135, -83.9) -> (142.5, -79.9)
  curve K4 (142.5, -79.9) -> (160, -86.9)
  line L7 (160, -88.5) -> (160, -86.9)
  line L8 (125, -88.5) -> (160, -88.5)
  line L9 (142.5, -86.9) -> (142.5, -79.9)
  line L10 (160, -86.9) -> (142.5, -86.9)
  point P11 (142.5, -79.9)
  point P14 (142.5, -79.9)
  point P15 (142.5, -86.9)
  point P12 (160, -86.9)
  point P16 (160, -86.9)
  coincident P11 P14
  coincident L3 P15
  perpendicular L3 L9
  coincident P12 P16
sweep "Sweep1" sketch "Schizzo14" TwistAngle 0 named "d254_1" TaperAngle 0 named "d255_1"
combine "Combina2"
extrude "Estrusione15" add of existing geometry blind 15 named "d256_1"
loft "Loft1"
extrude "Estrusione16" new body of existing geometry blind 32.5 named "d260_1"
surface_patch "ChiusuraSuperficie1"
step "Separa1"
surface_delete_face "FacciaEliminazioneSuperficie1"
surface_delete_face "FacciaEliminazioneSuperficie2"
surface_delete_face "FacciaEliminazioneSuperficie3"
surface_delete_face "FacciaEliminazioneSuperficie4"
extrude "Estrusione17" new body of existing geometry blind 32.5 named "d262_1"
surface_patch "ChiusuraSuperficie2"
surface_delete_face "FacciaEliminazioneSuperficie5"
step "RitagliaSuperficie1"
surface_stitch "UnisciSuperficie1" StitchingTolerence 0.1 named "d264_1"
surface_delete_face "FacciaEliminazioneSuperficie6"
combine "Combina3"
